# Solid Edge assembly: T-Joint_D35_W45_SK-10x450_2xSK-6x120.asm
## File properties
Author: fknapp
Template: iso metric assembly.asm
Last saved by: fknapp
Revision: 14
Application: Solid Edge
Username: fknapp
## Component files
T-Joint_D35_W45.par
SK Schraube 6x120_ohne_Gewinde.par
SK Schraube 10x450_ohne_Gewinde_22042020.par
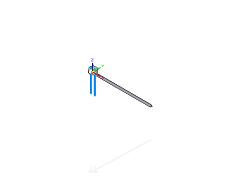
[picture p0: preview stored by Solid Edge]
